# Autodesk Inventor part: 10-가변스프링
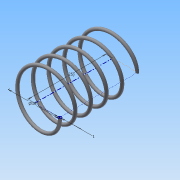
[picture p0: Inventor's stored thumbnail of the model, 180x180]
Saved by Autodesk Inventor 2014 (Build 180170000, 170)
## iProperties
Created: 2015-06
Part Number: 10-가변스프링
Material: 강철, 연강
Document SubType Name: Modeling
Designer: MYHOME
Density: 7.86 g/cm^3
Appearance: 강철
Mass: 1.52988 g
Surface Area: 7.87024 cm^2
Volume: 0.194641 cm^3
Author: MYHOME
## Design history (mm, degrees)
sketch "스케치1"
  geometry: L1 (0, 14.5)-(8, 14.5); L2 (8, 14.5)-(8, 0); L3 (8, 0)-(0, 0); L4 (0, 0)-(0, 14.5); C1 r 0.5 at (8, 0); 1 further point
  constraints: 8 end point, 3 coincident, 2 parallel, 1 centre point, 1 horizontal, 1 perpendicular
  dimensions: "d0" = 1 diameter of C1; "d1" = 16 diameter of L2 L4; "d2" = 14.5 distance of L3.end L1.start (derived)
feature "코일1" sketch "스케치1" pitch "d3" = 10; turns "d5" = 5; dims "d4" = 14.5 (= d2), "d6" = 0, angle "d7" = 90 deg, angle "d8" = 90 deg, "d9" = 0, "d10" = 0
sketch "스케치2"
  geometry: L1 (-8.5, 0)-(-7.5, 0) reference; 1 further point
  constraints: 1 horizontal alignment
extrude "돌출1" cut sketch "스케치2" stored distance "d11" = 10; taper "d12" = 0 deg
node "작업 평면1"
sketch "스케치3"
  geometry: L1 (-7.5, 0)-(-8.5, 0) reference; 1 further point
  constraints: 1 horizontal alignment
extrude "돌출2" cut sketch "스케치3" stored distance "d14" = 10; taper "d15" = 0 deg
node "솔리드1"
node "절단 모서리 투영1"
node "절단 모서리 투영2"
other parameters: "d13" = 14.5 (= d2)
